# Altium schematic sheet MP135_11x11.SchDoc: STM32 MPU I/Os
size A3; Date: Not used; ApprovedBy: Not used; CheckedBy: Not used; Author: Not used; CompanyName: STMicroelectronics; DrawnBy: Not used; Engineer: Not used; Organization: Not used; Address1: Not used; Address2: Not used; Address3: Not used; Address4: Not used; DocumentNumber: 3; Revision: Not used; SheetNumber: 3; SheetTotal: 17
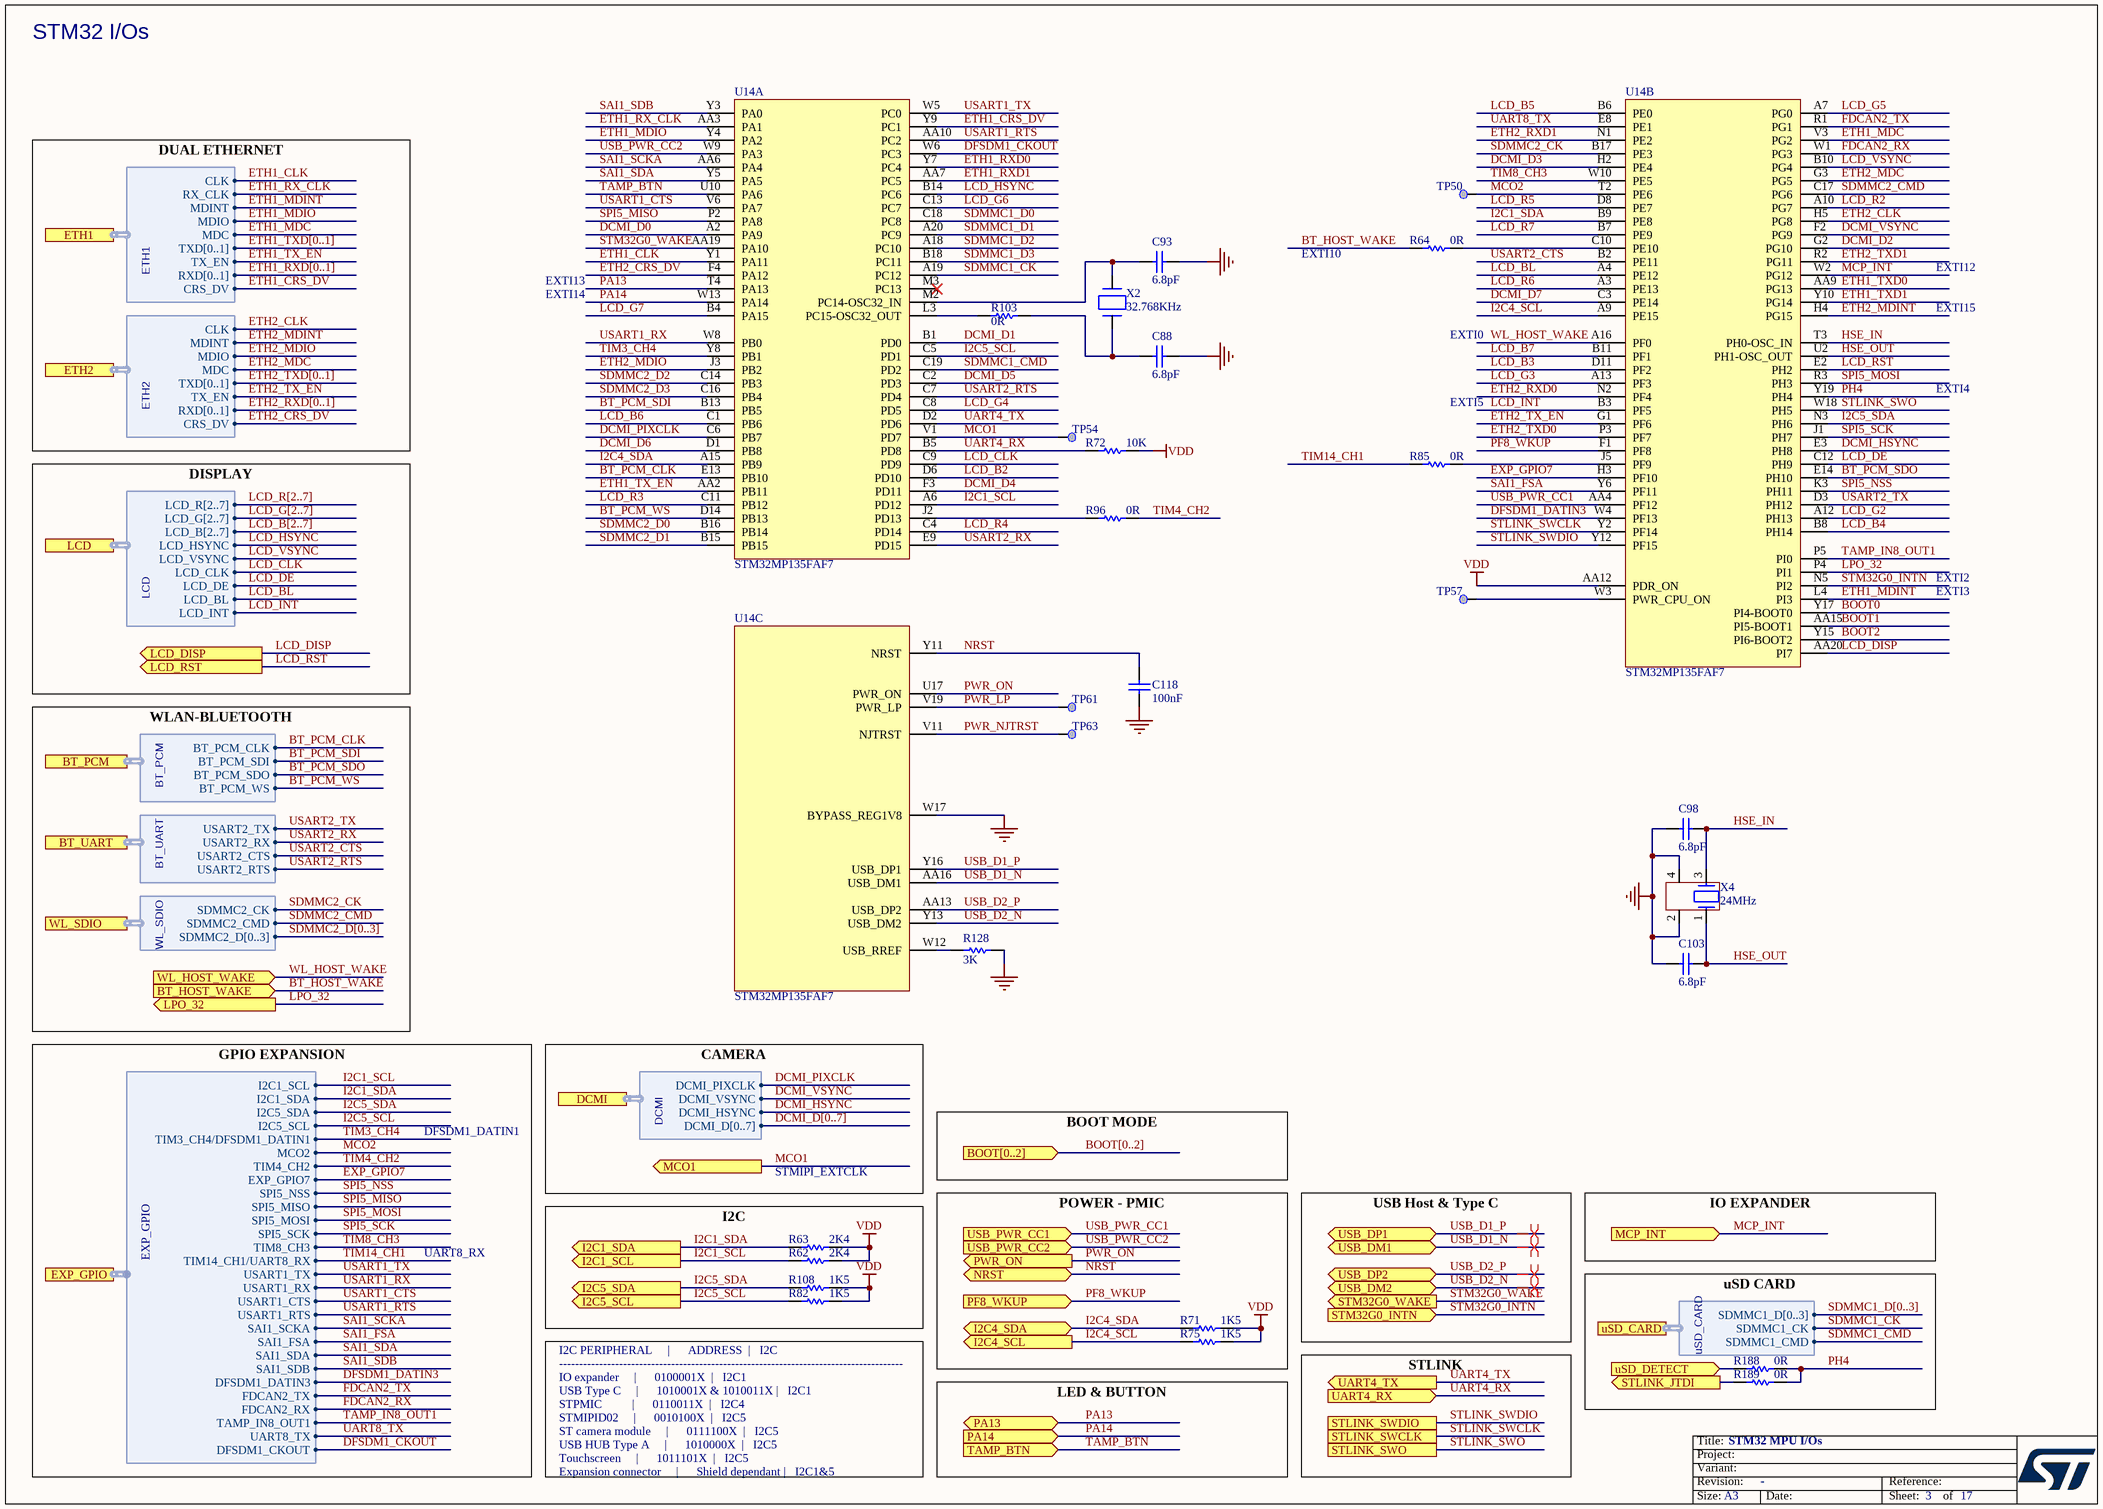
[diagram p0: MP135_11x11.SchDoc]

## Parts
C88  value 6.8pF  [C0402]  (hidden comment: Capacitor)
C93  value 6.8pF  [C0402]  (hidden comment: Capacitor)
C98  value 6.8pF  [C0402]  (hidden comment: Capacitor)
C103  value 6.8pF  [C0402]  (hidden comment: Capacitor)
C118  value 100nF  [C0402]  (hidden comment: Capacitor)
R62  value 2K4  [R0402]  (hidden comment: Resistor)
R63  value 2K4  [R0402]  (hidden comment: Resistor)
R64  value 0R  [R0402]  (hidden comment: Resistor)
R71  value 1K5  [R0402]  (hidden comment: Resistor)
R72  value 10K  [R0402]  (hidden comment: Resistor)
R75  value 1K5  [R0402]  (hidden comment: Resistor)
R82  value 1K5  [R0402]  (hidden comment: Resistor)
R85  value 0R  [R0402]  (hidden comment: Resistor)
R96  value 0R  [R0402]  (hidden comment: Resistor)
R103  value 0R  [R0402]  (hidden comment: Resistor)
R108  value 1K5  [R0402]  (hidden comment: Resistor)
R128  value 3K  [R0402]  (hidden comment: Resistor)
R188  value 0R  [R0402]  (hidden comment: Resistor)
R189  value 0R  [R0402]  (hidden comment: Resistor)
TP50  Test Point  [TP_SMD_1MM]  (value not drawn)  (no BOM)
TP54  Test Point  [TP_SMD_1MM]  (value not drawn)  (no BOM)
TP57  Test Point  [TP_SMD_1MM]  (value not drawn)  (no BOM)
TP61  Test Point  [TP_SMD_1MM]  (value not drawn)  (no BOM)
TP63  Test Point  [TP_SMD_1MM]  (value not drawn)  (no BOM)
U14  STM32MP135FAF7  [ICC_TFBGA320_11X11_STM32MP135FA7_P050_H1P20]  (parts A,B,C of 5)
X2  value 32.768KHz  [CRY_NX2012SA_2P]  (hidden comment: XTAL_2_PINS)
X4  value 24MHz  [CRY_NX2016SA_4P]  (hidden comment: XTAL_4_PINS)

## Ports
BOOT[0..2] (in), BT_HOST_WAKE (in), BT_PCM (harness BT_PCM), BT_UART (harness BT_UART), DCMI (harness DCMI), ETH1 (harness ETH1), ETH2 (harness ETH2), EXP_GPIO (harness EXP_GPIO), I2C1_SCL (out), I2C1_SDA (out), I2C4_SCL (out), I2C4_SDA (bidir), I2C5_SCL (out), I2C5_SDA (out), LCD (harness LCD), LCD_DISP (out), LCD_RST (out), LPO_32 (out), MCO1 (out), MCP_INT (in), NRST (bidir), PA13 (bidir), PA14 (in), PF8_WKUP (in), PWR_ON (out), STLINK_JTDI (out), STLINK_SWCLK, STLINK_SWDIO, STLINK_SWO, STM32G0_INTN (in), STM32G0_WAKE (out), TAMP_BTN (in), UART4_RX (in), UART4_TX (out), USB_DM1 (bidir), USB_DM2 (bidir), USB_DP1 (bidir), USB_DP2 (bidir), USB_PWR_CC1 (in), USB_PWR_CC2 (in), uSD_CARD (harness uSD_CARD), uSD_DETECT (in), WL_HOST_WAKE (in), WL_SDIO (harness WL_SDIO)

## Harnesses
BT_PCM: BT_PCM_CLK, BT_PCM_SDI, BT_PCM_SDO, BT_PCM_WS
BT_UART: USART2_TX, USART2_RX, USART2_CTS, USART2_RTS
WL_SDIO: SDMMC2_CMD, SDMMC2_CK, SDMMC2_D[0..3]
LCD: LCD_R[2..7], LCD_G[2..7], LCD_B[2..7], LCD_HSYNC, LCD_VSYNC, LCD_DE, LCD_CLK, LCD_BL, LCD_INT
DCMI: DCMI_D[0..7], DCMI_HSYNC, DCMI_VSYNC, DCMI_PIXCLK
ETH2: MDINT, TXD[0..1], MDIO, MDC, TX_EN, RXD[0..1], CRS_DV, CLK
ETH1: MDINT, TXD[0..1], MDIO, MDC, RX_CLK, TX_EN, RXD[0..1], CRS_DV, CLK
uSD_CARD: SDMMC1_D[0..3], SDMMC1_CK, SDMMC1_CMD
EXP_GPIO: I2C1_SCL, I2C1_SDA, I2C5_SDA, MCO2, TIM8_CH3, DFSDM1_DATIN3, SPI5_NSS, SPI5_MISO, SPI5_MOSI, SPI5_SCK, TIM4_CH2, USART1_TX, USART1_RX, USART1_CTS, USART1_RTS, UART8_TX, TIM14_CH1/UART8_RX, FDCAN2_TX, FDCAN2_RX, DFSDM1_CKOUT, TIM3_CH4/DFSDM1_DATIN1, I2C5_SCL, SAI1_SCKA, SAI1_FSA, SAI1_SDA, SAI1_SDB, TAMP_IN8_OUT1, EXP_GPIO7

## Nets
GND: C88.2 C93.2 C98.1 C103.2 C118.2 R128.2 U14.W17(BYPASS_REG1V8) X4.2 X4.4
VDD: R62.2 R63.2 R71.2 R72.2 R75.2 R82.2 R108.2 U14.AA12(PDR_ON)
BOOT0: U14.Y17(PI4-BOOT0)
BOOT1: U14.AA15(PI5-BOOT1)
BOOT2: U14.Y15(PI6-BOOT2)
BT_HOST_WAKE: R64.1 ; port BT_HOST_WAKE
BT_PCM_CLK: U14.E13(PB10) ; port BT_PCM.BT_PCM_CLK
BT_PCM_SDI: U14.B13(PB5) ; port BT_PCM.BT_PCM_SDI
BT_PCM_SDO: U14.E14(PH10) ; port BT_PCM.BT_PCM_SDO
BT_PCM_WS: U14.D14(PB13) ; port BT_PCM.BT_PCM_WS
DCMI_D0: U14.A2(PA9)
DCMI_D1: U14.B1(PD0)
DCMI_D2: U14.G2(PG10)
DCMI_D3: U14.H2(PE4)
DCMI_D4: U14.F3(PD11)
DCMI_D5: U14.C2(PD3)
DCMI_D6: U14.D1(PB8)
DCMI_D7: U14.C3(PE14)
DCMI_HSYNC: U14.E3(PH8) ; port DCMI.DCMI_HSYNC
DCMI_PIXCLK: U14.C6(PB7) ; port DCMI.DCMI_PIXCLK
DCMI_VSYNC: U14.F2(PG9) ; port DCMI.DCMI_VSYNC
DFSDM1_CKOUT: U14.W6(PC3) ; port EXP_GPIO.DFSDM1_CKOUT
DFSDM1_DATIN3: U14.W4(PF13) ; port EXP_GPIO.DFSDM1_DATIN3
ETH1_CLK: U14.Y1(PA11) ; port ETH1.CLK
ETH1_CRS_DV: U14.Y9(PC1) ; port ETH1.CRS_DV
ETH1_MDC: U14.V3(PG2) ; port ETH1.MDC
ETH1_MDINT: U14.L4(PI3) ; port ETH1.MDINT
ETH1_MDIO: U14.Y4(PA2) ; port ETH1.MDIO
ETH1_RX_CLK: U14.AA3(PA1) ; port ETH1.RX_CLK
ETH1_RXD0: U14.Y7(PC4)
ETH1_RXD1: U14.AA7(PC5)
ETH1_TX_EN: U14.AA2(PB11) ; port ETH1.TX_EN
ETH1_TXD0: U14.AA9(PG13)
ETH1_TXD1: U14.Y10(PG14)
ETH2_CLK: U14.H5(PG8) ; port ETH2.CLK
ETH2_CRS_DV: U14.F4(PA12) ; port ETH2.CRS_DV
ETH2_MDC: U14.G3(PG5) ; port ETH2.MDC
ETH2_MDINT: U14.H4(PG15) ; port ETH2.MDINT
ETH2_MDIO: U14.J3(PB2) ; port ETH2.MDIO
ETH2_RXD0: U14.N2(PF4)
ETH2_RXD1: U14.N1(PE2)
ETH2_TX_EN: U14.G1(PF6) ; port ETH2.TX_EN
ETH2_TXD0: U14.P3(PF7)
ETH2_TXD1: U14.R2(PG11)
EXP_GPIO7: U14.H3(PF10) ; port EXP_GPIO.EXP_GPIO7
FDCAN2_RX: U14.W1(PG3) ; port EXP_GPIO.FDCAN2_RX
FDCAN2_TX: U14.R1(PG1) ; port EXP_GPIO.FDCAN2_TX
HSE_IN: C98.2 U14.T3(PH0-OSC_IN) X4.3
HSE_OUT: C103.1 U14.U2(PH1-OSC_OUT) X4.1
I2C1_SCL: R62.1 U14.A6(PD12) ; port I2C1_SCL, port EXP_GPIO.I2C1_SCL
I2C1_SDA: R63.1 U14.B9(PE8) ; port I2C1_SDA, port EXP_GPIO.I2C1_SDA
I2C4_SCL: R75.1 U14.A9(PE15) ; port I2C4_SCL
I2C4_SDA: R71.1 U14.A15(PB9) ; port I2C4_SDA
I2C5_SCL: R82.1 U14.C5(PD1) ; port I2C5_SCL, port EXP_GPIO.I2C5_SCL
I2C5_SDA: R108.1 U14.N3(PH6) ; port I2C5_SDA, port EXP_GPIO.I2C5_SDA
LCD_B2: U14.D6(PD10)
LCD_B3: U14.D11(PF2)
LCD_B4: U14.B8(PH14)
LCD_B5: U14.B6(PE0)
LCD_B6: U14.C1(PB6)
LCD_B7: U14.B11(PF1)
LCD_BL: U14.A4(PE12) ; port LCD.LCD_BL
LCD_CLK: U14.C9(PD9) ; port LCD.LCD_CLK
LCD_DE: U14.C12(PH9) ; port LCD.LCD_DE
LCD_DISP: U14.AA20(PI7) ; port LCD_DISP
LCD_G2: U14.A12(PH13)
LCD_G3: U14.A13(PF3)
LCD_G4: U14.C8(PD5)
LCD_G5: U14.A7(PG0)
LCD_G6: U14.C13(PC7)
LCD_G7: U14.B4(PA15)
LCD_HSYNC: U14.B14(PC6) ; port LCD.LCD_HSYNC
LCD_INT: U14.B3(PF5) ; port LCD.LCD_INT
LCD_R2: U14.A10(PG7)
LCD_R3: U14.C11(PB12)
LCD_R4: U14.C4(PD14)
LCD_R5: U14.D8(PE7)
LCD_R6: U14.A3(PE13)
LCD_R7: U14.B7(PE9)
LCD_RST: U14.E2(PH2) ; port LCD_RST
LCD_VSYNC: U14.B10(PG4) ; port LCD.LCD_VSYNC
LPO_32: U14.P4(PI1) ; port LPO_32
MCO1: TP54.1 U14.V1(PD7) ; port MCO1
MCO2: TP50.1 U14.T2(PE6) ; port EXP_GPIO.MCO2
MCP_INT: U14.W2(PG12) ; port MCP_INT
NRST: C118.1 U14.Y11(NRST) ; port NRST
PA13: U14.T4(PA13) ; port PA13
PA14: U14.W13(PA14) ; port PA14
PF8_WKUP: U14.F1(PF8) ; port PF8_WKUP
PH4: R188.2 R189.2 U14.Y19(PH4)
PWR_LP: TP61.1 U14.V19(PWR_LP)
PWR_NJTRST: TP63.1 U14.V11(NJTRST)
PWR_ON: U14.U17(PWR_ON) ; port PWR_ON
SAI1_FSA: U14.Y6(PF11) ; port EXP_GPIO.SAI1_FSA
SAI1_SCKA: U14.AA6(PA4) ; port EXP_GPIO.SAI1_SCKA
SAI1_SDA: U14.Y5(PA5) ; port EXP_GPIO.SAI1_SDA
SAI1_SDB: U14.Y3(PA0) ; port EXP_GPIO.SAI1_SDB
SDMMC1_CK: U14.A19(PC12) ; port uSD_CARD.SDMMC1_CK
SDMMC1_CMD: U14.C19(PD2) ; port uSD_CARD.SDMMC1_CMD
SDMMC1_D0: U14.C18(PC8)
SDMMC1_D1: U14.A20(PC9)
SDMMC1_D2: U14.A18(PC10)
SDMMC1_D3: U14.B18(PC11)
SDMMC2_CK: U14.B17(PE3) ; port WL_SDIO.SDMMC2_CK
SDMMC2_CMD: U14.C17(PG6) ; port WL_SDIO.SDMMC2_CMD
SDMMC2_D0: U14.B16(PB14)
SDMMC2_D1: U14.B15(PB15)
SDMMC2_D2: U14.C14(PB3)
SDMMC2_D3: U14.C16(PB4)
SPI5_MISO: U14.P2(PA8) ; port EXP_GPIO.SPI5_MISO
SPI5_MOSI: U14.R3(PH3) ; port EXP_GPIO.SPI5_MOSI
SPI5_NSS: U14.K3(PH11) ; port EXP_GPIO.SPI5_NSS
SPI5_SCK: U14.J1(PH7) ; port EXP_GPIO.SPI5_SCK
STLINK_JTDI: R189.1 ; port STLINK_JTDI
STLINK_SWCLK: U14.Y2(PF14) ; port STLINK_SWCLK
STLINK_SWDIO: U14.Y12(PF15) ; port STLINK_SWDIO
STLINK_SWO: U14.W18(PH5) ; port STLINK_SWO
STM32G0_INTN: U14.N5(PI2) ; port STM32G0_INTN
STM32G0_WAKE: U14.AA19(PA10) ; port STM32G0_WAKE
TAMP_BTN: U14.U10(PA6) ; port TAMP_BTN
TAMP_IN8_OUT1: U14.P5(PI0) ; port EXP_GPIO.TAMP_IN8_OUT1
TIM3_CH4: U14.Y8(PB1) ; port EXP_GPIO.TIM3_CH4/DFSDM1_DATIN1
TIM4_CH2: R96.2 ; port EXP_GPIO.TIM4_CH2
TIM8_CH3: U14.W10(PE5) ; port EXP_GPIO.TIM8_CH3
TIM14_CH1: R85.1 ; port EXP_GPIO.TIM14_CH1/UART8_RX
UART4_RX: R72.1 U14.B5(PD8) ; port UART4_RX
UART4_TX: U14.D2(PD6) ; port UART4_TX
UART8_TX: U14.E8(PE1) ; port EXP_GPIO.UART8_TX
USART1_CTS: U14.V6(PA7) ; port EXP_GPIO.USART1_CTS
USART1_RTS: U14.AA10(PC2) ; port EXP_GPIO.USART1_RTS
USART1_RX: U14.W8(PB0) ; port EXP_GPIO.USART1_RX
USART1_TX: U14.W5(PC0) ; port EXP_GPIO.USART1_TX
USART2_CTS: U14.B2(PE11) ; port BT_UART.USART2_CTS
USART2_RTS: U14.C7(PD4) ; port BT_UART.USART2_RTS
USART2_RX: U14.E9(PD15) ; port BT_UART.USART2_RX
USART2_TX: U14.D3(PH12) ; port BT_UART.USART2_TX
USB_D1_N: U14.AA16(USB_DM1) ; port USB_DM1
USB_D1_P: U14.Y16(USB_DP1) ; port USB_DP1
USB_D2_N: U14.Y13(USB_DM2) ; port USB_DM2
USB_D2_P: U14.AA13(USB_DP2) ; port USB_DP2
USB_PWR_CC1: U14.AA4(PF12) ; port USB_PWR_CC1
USB_PWR_CC2: U14.W9(PA3) ; port USB_PWR_CC2
uSD_DETECT: R188.1 ; port uSD_DETECT
WL_HOST_WAKE: U14.A16(PF0) ; port WL_HOST_WAKE
NetC88_1: C88.1 R103.2 X2.1(X1)
NetC93_1: C93.1 U14.M2(PC14-OSC32_IN) X2.2(X2)
NetR64_2: R64.2 U14.C10(PE10)
NetR85_2: R85.2 U14.J5(PF9)
NetR96_1: R96.1 U14.J2(PD13)
NetR103_1: R103.1 U14.L3(PC15-OSC32_OUT)
NetR128_1: R128.1 U14.W12(USB_RREF)
NetTP57_1: TP57.1 U14.W3(PWR_CPU_ON)

Not connected (* = marked no-connect by the designer): U14 M3(PC13)*

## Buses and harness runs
bus BOOT[0..2] = port BOOT[0..2]
bus DCMI_D[0..7]
bus ETH1_RXD[0..1]
bus ETH1_TXD[0..1]
bus ETH2_RXD[0..1]
bus ETH2_TXD[0..1]
bus LCD_B[2..7]
bus LCD_G[2..7]
bus LCD_R[2..7]
bus SDMMC1_D[0..3]
bus SDMMC2_D[0..3]

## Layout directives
differential pair: USB_D1_N, USB_D1_P, USB_D2_N, USB_D2_P

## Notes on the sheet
- STM32 I/Os
- EXTI14
- EXTI13
- EXTI10
- EXTI12
- EXTI15
- EXTI0
- DUAL ETHERNET
- EXTI5
- EXTI4
- EXTI2
- EXTI3
- DISPLAY
- WLAN-BLUETOOTH
- DFSDM1_DATIN1
- CAMERA
- STMIPI_EXTCLK
- BOOT MODE
- UART8_RX
- IO EXPANDER
- I2C
- POWER - PMIC
- USB Host & Type C
- uSD CARD
- GPIO EXPANSION
- I2C PERIPHERAL	    |      ADDRESS		|   I2C
  --------------------------------------------------------------------------------------
  IO expander	    |      0100001X		|   I2C1
  USB Type C	    |      1010001X & 1010011X	|   I2C1
  STPMIC	    	    |      0110011X		|   I2C4
  STMIPID02	    |      0010100X		|   I2C5
  ST camera module	    |      0111100X		|   I2C5
  USB HUB Type A	    |      1010000X		|   I2C5
  Touchscreen	    |      1011101X		|   I2C5
  Expansion connector	    |      Shield dependant	|   I2C1&5
- LED & BUTTON
- STLINK

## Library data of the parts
C88 C93 C98 C103 = MCD-00674: Capacitor, MLCC, 6.8pF, 50V, NPO, +/-0.25pF, 0402, T=0.5mm; Manufacturer_Part_Number: CC0402CRNPO9BN6R8; Manufacturer: YAGEO; Part_Preference: Recommended; Component_Country_Of_Origin: China; ShowFields: YES; ID: 3068
C118 = MCD-00006: Capacitor, MLCC, 100nF, 16V, X7R, +/-10%, 0402, T=0.5mm; Manufacturer_Part_Number: CC0402KRX7R7BB104; Manufacturer: YAGEO; Part_Preference: Recommended; Partial_Alternate_Internal_Part_Number: MCD-03299; Order_Code_RS: 9402047; Component_Country_Of_Origin: China; ShowFields: YES; ID: 2474
R62 R63 = MCD-00433: Resistor, 2K4, 0402, +/-1%, 1/16W; Part_Preference: Recommended; Manufacturer: YAGEO; Manufacturer_Part_Number: RC0402FR-072K4L; Component_Country_Of_Origin: China; ShowFields: YES; ID: 2843
R64 R85 R96 R188 R189 = MCD-00052: Resistor, 0R, 0402, +/-5%, 1/16W; Part_Preference: Recommended; Manufacturer: YAGEO; Manufacturer_Part_Number: RC0402JR-070RL; Order_Code_RS: 9232516RL; Component_Country_Of_Origin: China; ShowFields: YES; ID: 2540
R71 R75 R82 R108 = MCD-00068: Resistor, 1K5, 0402, +/-1%, 1/16W; Part_Preference: Recommended; Manufacturer: YAGEO; Manufacturer_Part_Number: RC0402FR-071K5L; Order_Code_RS: 9239251; Component_Country_Of_Origin: China; ShowFields: YES; ID: 2524
R72 = MCD-00053: Resistor, 10K, 0402, +/-1%, 1/16W; Manufacturer_Part_Number: RC0402FR-0710KL; Manufacturer: YAGEO; BMS_Part_Number: 9131590; Part_Preference: Recommended; Order_Code_RS: 9239359; Component_Country_Of_Origin: China; ShowFields: YES; ID: 2539
R103 = MCD-00052: Resistor, 0R, 0402, +/-5%, 1/16W; Manufacturer_Part_Number: RC0402JR-070RL; Manufacturer: YAGEO; Part_Preference: Recommended; Order_Code_RS: 9232516RL; Component_Country_Of_Origin: China; ShowFields: YES; ID: 2540
R128 = MCD-00185: Resistor, 3K, 0402, +/-1%, 1/16W; Part_Preference: Recommended; Manufacturer: YAGEO; Manufacturer_Part_Number: RC0402FR-073KL; Component_Country_Of_Origin: China; ShowFields: YES; ID: 2682
TP50 TP54 TP57 TP61 TP63 = MCD-00074: Test Point 1mm; Part_Type: Misc; Part_Preference: Recommended; ShowFields: YES; ID: 2518; Component_Country_Of_Origin: Unknown
U14 = MCD-02251: Cortex-A7 @ 900MHz, 128KB-ROM, 128KB-SRAM, 2x Ethernet, 2x ADC, 2x CAN FD, TSC, Camera, Display, Secure Boot, Cryptography, DRAM enc/dec, PKA; Part_Preference: Recommended; Part_Type: IC; Manufacturer: STMICROELECTRONICS; Manufacturer_HQ_COO: EU; Component_Country_Of_Origin: Unknown; ShowFields: YES; ID: 4351
X2 = MCD-01479: Crystal, 32.768kHz, 6pF, +/-20ppm, 80K, 2.05x1.2mm; Part_Type: Crystal_Osc; Manufacturer_Part_Number: NX2012SA-32.768KHZ-EXS00A-MU00527; Manufacturer: NDK; BMS_Part_Number: 9157049; Part_Preference: Recommended; Component_Country_Of_Origin: Japan; ShowFields: YES; ID: 3579
X4 = MCD-01036: Crystal, 24MHz, 6pF, +/-20ppm, 80R, 2x1.6mm; BMS_Part_Number: 9157045; Part_Type: Crystal_Osc; Part_Preference: Recommended; Manufacturer: NDK; Manufacturer_Part_Number: NX2016SA-24MHZ-EXS00A-CS10820; Component_Country_Of_Origin: Japan; ShowFields: YES; ID: 2989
